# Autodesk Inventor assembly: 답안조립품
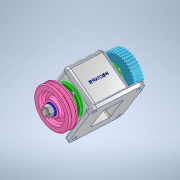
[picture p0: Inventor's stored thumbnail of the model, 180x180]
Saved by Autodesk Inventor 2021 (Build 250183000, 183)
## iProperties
Created: 2022-07
Part Number: 답안조립품
Document SubType Name: Assembly
Designer: i
Author: i
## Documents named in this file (12)
- C:\Users\i\Desktop\720706V1001\답안조립품.iam
- C:\Users\i\Desktop\720706V1001\본체.ipt
- C:\Users\i\Desktop\720706V1001\V벨트풀리.ipt
- C:\Users\i\Desktop\720706V1001\너트 M12x1.25.ipt
- C:\Users\i\Desktop\720706V1001\베어링 6204.ipt
- C:\Users\i\Desktop\720706V1001\볼트 M4x0.7.ipt
- C:\Users\i\Desktop\720706V1001\스퍼기어.ipt
- C:\Users\i\Desktop\720706V1001\오일실 20x35x8.ipt
- C:\Users\i\Desktop\720706V1001\와셔 12x24.ipt
- C:\Users\i\Desktop\720706V1001\축.ipt
- C:\Users\i\Desktop\720706V1001\커버.ipt
- C:\Users\i\Desktop\720706V1001\키 5x5.ipt
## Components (1 placed, 1 different names)
1. V벨트풀리:1
## Named parameters: d11_d9 = 0, d12_d10 = 0
